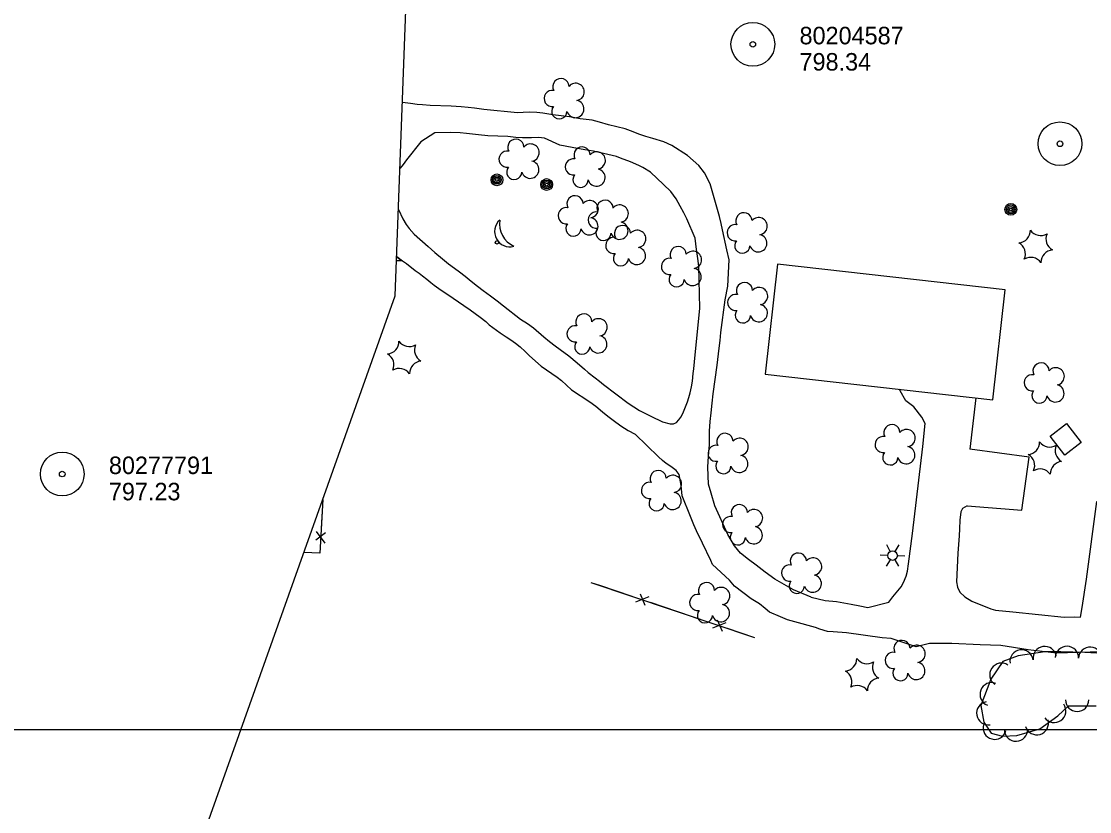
# Model space of a CAD drawing. Extents: x 591954 to 597000, y 198576 to 213500.
# Drawn here: x 593553.2 to 593919.4, y 211471.8 to 211742.7 of the extents above; entities that cross this region are included whole.
import ezdxf

# ---------------------------------------------------------------- set-up
doc = ezdxf.new("R2010")
doc.units = 0
for name, color, linetype in [('Level 10', 7, 'Continuous'), ('Level 12', 7, 'Continuous'), ('Level 14', 7, 'Continuous'), ('Level 15', 7, 'Continuous'), ('Level 17', 7, 'Continuous'), ('Level 18', 7, 'Continuous'), ('Level 4', 7, 'Continuous'), ('Level 6', 7, 'Continuous')]:
    doc.layers.add(name, color=color, linetype=linetype)

msp = doc.modelspace()

# ---------------------------------------------------------------- linework, layer by layer
at = {"layer": 'Level 10'}
msp.add_line((593000, 211500), (595000, 211500), dxfattribs=at)
msp.add_line((593000, 211500), (595000, 211500), dxfattribs=at)
at = {"layer": 'Level 12'}
for points in [[(593890.46, 211650.69), (593812.36, 211659.45), (593808.13, 211621.76), (593886.23, 211612.99), (593890.46, 211650.69)], [(593911.42, 211604.9), (593916.47, 211598.39), (593910.88, 211594.05), (593905.82, 211600.56), (593911.42, 211604.9)]]:
    msp.add_lwpolyline(points, dxfattribs=at)
msp.add_circle((593716.19, 211666.96), 0.562, dxfattribs=at)
for centre, radius, start, end in [((593720.6, 211670.69), 5.22, 131.2001, 285.4985), ((593725.63, 211673.4), 8.55, 171.8557, 244.8398)]:
    msp.add_arc(centre, radius, start, end, dxfattribs=at)
at = {"layer": 'Level 14'}
for p, q in [((593851.02, 211561.02), (593849.83, 211563.32)), ((593852.72, 211561.01), (593854.09, 211563.24)), ((593850.19, 211559.66), (593847.58, 211559.73)), ((593850.94, 211558.17), (593849.58, 211555.98)), ((593852.58, 211558.12), (593853.82, 211555.95)), ((593853.46, 211559.57), (593855.98, 211559.5))]:
    msp.add_line(p, q, dxfattribs=at)
for centre, radius in [((593716.19, 211688.4), 2.02), ((593716.18, 211688.41), 1.52), ((593716.19, 211688.37), 1.01), ((593716.19, 211688.38), 0.502), ((593733.24, 211686.81), 2.02), ((593733.24, 211686.82), 1.52), ((593733.24, 211686.79), 1.01), ((593733.25, 211686.8), 0.502), ((593892.34, 211678.27), 2.02), ((593892.34, 211678.28), 1.52), ((593892.34, 211678.24), 1.01), ((593892.35, 211678.25), 0.502), ((593851.82, 211559.59), 1.64)]:
    msp.add_circle(centre, radius, dxfattribs=at)
at = {"layer": 'Level 15'}
for p, q in [((593657.41, 211567.44), (593654.09, 211564.82)), ((593654.18, 211567.79), (593657.22, 211563.9)), ((593767.06, 211542.46), (593765.42, 211546.35)), ((593768.26, 211545.47), (593763.7, 211543.59)), ((593794.66, 211536.57), (593790.1, 211534.69)), ((593793.46, 211533.56), (593791.83, 211537.45))]:
    msp.add_line(p, q, dxfattribs=at)
for points in [[(593656.52, 211578.79), (593655.53, 211560.45), (593650.05, 211560.61)], [(593656.52, 211578.79), (593655.98, 211568.85)], [(593655.63, 211562.28), (593655.53, 211560.45), (593650.05, 211560.61)], [(593804.64, 211531.37), (593748.48, 211550.3)], [(593751.83, 211549.17), (593748.48, 211550.3)], [(593762.56, 211545.55), (593751.83, 211549.17)], [(593778.24, 211540.27), (593768.8, 211543.45)], [(593788.96, 211536.65), (593778.24, 211540.27)], [(593804.64, 211531.37), (593795.2, 211534.55)]]:
    msp.add_lwpolyline(points, dxfattribs=at)
at = {"layer": 'Level 17'}
for points in [[(593823.89, 211545.38), (593817.91, 211547.86), (593811.51, 211551.53), (593808.15, 211553.86), (593805.06, 211556.26), (593802.43, 211558.19), (593799.65, 211560.45), (593797.64, 211562.88), (593795.29, 211566.82), (593790.87, 211576.64), (593789.6, 211581.03), (593788.73, 211584.07), (593788.53, 211589.94), (593788.74, 211593.67), (593789.07, 211597.61), (593789.02, 211602.25), (593789.28, 211605.59), (593789.64, 211608.54), (593790.03, 211611.84), (593790.3, 211615.03), (593791.74, 211624.89), (593792.39, 211630.71), (593792.76, 211633.36), (593792.97, 211636.12), (593794.39, 211647.25), (593795.34, 211651.93), (593795.77, 211661.01), (593794.95, 211664.4), (593793.48, 211671.31), (593793.08, 211673.5), (593792.44, 211675.83), (593789.28, 211687.07), (593787.31, 211690.86), (593785.43, 211693.31), (593781.49, 211696.72), (593776.2, 211700.22), (593773.36, 211701.48), (593769.62, 211702.57), (593767.2, 211703.27), (593764.89, 211704.08), (593762.85, 211704.9), (593760.15, 211705.86), (593754.46, 211707.33), (593751.34, 211708.22), (593748.89, 211708.83), (593744.73, 211709.38), (593741.11, 211709.96), (593735.36, 211710.68), (593731.93, 211711.25), (593729.83, 211711.48), (593727.29, 211711.57), (593725.24, 211711.5), (593723.22, 211711.38), (593711.71, 211712.48), (593708.55, 211713.04), (593706.37, 211713.23), (593703.89, 211713.41), (593700.49, 211713.65), (593693.33, 211713.93), (593690.66, 211714.15), (593688.8, 211714.3), (593686.59, 211714.6), (593683.84, 211714.97)], [(593694.9, 211704.51), (593690.12, 211701.49), (593685.18, 211695.27), (593684.03, 211693.71), (593683.04, 211692.38), (593682.99, 211692.28)], [(593757.19, 211696.44), (593751.21, 211697.83), (593749.34, 211698.22), (593746.3, 211698.69), (593741.94, 211699.48), (593737.77, 211700.26), (593732.55, 211702.65), (593730.43, 211702.89), (593728.03, 211702.76), (593724.92, 211702.78), (593722.7, 211702.96), (593719.92, 211703.23), (593713.1, 211703.54), (593709.88, 211703.85), (593705.75, 211704.35), (593703.64, 211704.53), (593700.14, 211704.63), (593694.9, 211704.51)], [(593687.78, 211669.82), (593692.58, 211665.59), (593694.92, 211663.51), (593697.55, 211661.29), (593699.58, 211659.67), (593701.61, 211658.15), (593703.34, 211656.86), (593705.26, 211655.35), (593707.38, 211653.68), (593709.54, 211651.95), (593711.5, 211650.47), (593713.98, 211648.67), (593716.31, 211646.9), (593718.45, 211645.2), (593724.3, 211640.67), (593726.65, 211639.11), (593728.68, 211637.68), (593732.22, 211634.57), (593734.16, 211633.02), (593736.16, 211631.51), (593737.86, 211630.27), (593740.84, 211628.03), (593743.65, 211625.7), (593746.21, 211623.45), (593747.5, 211622.39), (593749.86, 211620.54), (593751.41, 211619.36), (593752.76, 211618.28), (593761.17, 211611.85), (593765.12, 211609.38), (593768.93, 211607.44), (593772.94, 211605.5), (593775.53, 211604.75), (593776.76, 211604.71), (593777.77, 211605.24), (593778.56, 211606.08), (593779.26, 211607.05), (593779.9, 211608.28), (593780.88, 211610.6), (593781.51, 211612.29), (593781.96, 211613.79), (593782.46, 211615.4), (593782.9, 211617.41), (593783.2, 211619.4), (593783.49, 211622.02), (593783.68, 211623.63), (593783.89, 211626.03), (593785.72, 211644.45), (593785.39, 211658.82), (593785.05, 211661.46), (593784.61, 211664.52), (593784.17, 211668.37), (593781.3, 211675.08), (593780.3, 211677.11), (593779.06, 211679.4), (593777.62, 211681.86), (593775.86, 211684.45), (593773.32, 211686.85), (593768.89, 211691.01), (593766.25, 211692.64), (593765.07, 211693.19), (593762.81, 211694.24), (593761.36, 211694.81), (593759.18, 211695.66), (593757.19, 211696.44)], [(593682.99, 211692.28), (593682.99, 211692.28)], [(593682.47, 211678.23), (593683.9, 211675.07), (593685.03, 211673.07), (593686.08, 211671.68), (593687.78, 211669.82)], [(593682.47, 211678.23), (593682.47, 211678.23)], [(593681.86, 211662.09), (593683.82, 211660.7), (593681.81, 211660.67)], [(593681.86, 211662.04), (593682.6, 211661.47), (593683.82, 211660.7), (593685.22, 211659.69), (593688.21, 211657.34), (593689.48, 211656.37), (593690.64, 211655.49), (593692.12, 211654.32), (593693.49, 211653.2), (593694.7, 211652.31), (593696.23, 211651.2), (593697.79, 211650.13), (593699.42, 211649.09), (593701.23, 211647.88), (593703.02, 211646.62), (593704.84, 211645.31), (593707, 211643.79), (593708.7, 211642.62), (593710.5, 211641.34), (593712.34, 211639.81), (593713.54, 211638.75), (593717.28, 211635.91), (593719.4, 211634.54), (593720.99, 211633.51), (593722.53, 211632.46), (593724.19, 211631.16), (593725.91, 211629.55), (593727.38, 211628.11), (593731.35, 211624.57), (593734.97, 211622.07), (593736.89, 211620.8), (593738.34, 211619.64), (593741.78, 211616.36), (593748.09, 211612.3), (593750.1, 211610.81), (593752.34, 211608.92), (593754.21, 211607.41), (593756.05, 211606.02), (593758.69, 211604.07), (593761.22, 211602.44), (593763.59, 211601.26)], [(593823.89, 211545.38), (593828.73, 211544.21), (593832.63, 211543.8), (593837.61, 211542.88), (593840.57, 211542.32), (593843.31, 211541.84), (593850.55, 211543.62), (593851.86, 211545.43), (593854.77, 211548.86), (593855.61, 211550.37), (593856.48, 211552.49), (593856.9, 211554.19), (593857.22, 211556.76), (593858.7, 211567.18), (593862.22, 211596.94), (593862.97, 211604.92), (593861.82, 211607.04), (593859.07, 211610.54), (593856.34, 211612.64), (593854.43, 211616.04), (593854.23, 211616.59)], [(593880.33, 211613.66), (593878.33, 211596.1)], [(593825.37, 211534.91), (593818.36, 211536.91), (593815.81, 211537.61), (593813.39, 211538.64), (593809.63, 211540.18), (593808.12, 211541.44), (593806.23, 211542.99), (593803.39, 211544.78), (593797.68, 211549.07), (593795.89, 211551.13), (593790.12, 211556.55), (593789.54, 211557.9), (593786.69, 211563.81), (593784.55, 211568.04), (593783.71, 211570.14), (593782.52, 211572.96), (593779.71, 211580.11), (593779.32, 211583.57), (593778.68, 211587.43), (593777.65, 211588.73), (593775.77, 211590.18), (593774.19, 211591.15), (593772.98, 211592.14), (593771.53, 211593.49), (593763.59, 211601.26)], [(593877.39, 211576.63), (593896.17, 211575.17), (593898.65, 211593.36), (593878.33, 211596.1)], [(593877.39, 211576.63), (593875.75, 211575.69), (593875.16, 211574.57), (593874.82, 211571.75), (593874.74, 211568.76), (593874.69, 211566.31), (593874.15, 211560.46), (593873.78, 211550.59), (593874.05, 211548.77), (593874.92, 211547.08), (593876.6, 211545.47), (593878.98, 211543.99), (593880.38, 211543.4), (593883.51, 211542.11), (593885.54, 211541.34), (593887.14, 211540.9), (593893.06, 211540.27), (593910.61, 211538.44), (593914.14, 211538.54), (593916.25, 211538.52)], [(593916.25, 211538.52), (593916.84, 211541.75), (593918.25, 211551.52), (593921.84, 211578.14), (593941.02, 211576.26), (593952.89, 211575.5), (593970.78, 211573.96)], [(593923.32, 211526.63), (593908.05, 211526.13), (593898.28, 211527.3), (593888.95, 211528.72), (593881.85, 211529.02), (593872.18, 211529.47), (593864.51, 211529.42), (593859.93, 211528.33), (593851.31, 211531.17), (593848.29, 211531.41), (593836, 211533.08), (593831.49, 211533.47), (593829.48, 211533.61), (593826.84, 211534.31), (593825.37, 211534.91)]]:
    msp.add_lwpolyline(points, dxfattribs=at)
at = {"layer": 'Level 18'}
for points in [[(593925.78, 211525.95), (593917.74, 211526.4), (593909.5, 211526.63), (593904.06, 211526.6), (593894.84, 211525.2), (593889.61, 211523.23)], [(593889.61, 211523.23), (593885.55, 211517.17), (593882.05, 211508.2), (593883.05, 211502.43), (593885.61, 211498.74), (593889.51, 211497.72), (593894.36, 211497.85), (593902.26, 211500.24), (593908.5, 211504.67), (593912.09, 211508.02), (593921.59, 211508.06)]]:
    msp.add_lwpolyline(points, dxfattribs=at)
for centre, radius, start, end in [((593738.13, 211720.4), 2.78, 1.3946, 209.1675), ((593735.13, 211716.33), 2.78, 78.0716, 279.0826), ((593743.17, 211718.55), 2.97, 278.4237, 139.6575), ((593743.06, 211712.69), 2.97, 196.0745, 79.0477), ((593737.59, 211711.93), 2.61, 140.7797, 358.7123), ((593722.67, 211699.6), 2.78, 1.3946, 209.1675), ((593727.72, 211697.74), 2.97, 278.4237, 139.6575), ((593719.67, 211695.52), 2.78, 78.0716, 279.0826), ((593745.38, 211696.92), 2.78, 1.3946, 209.1675), ((593750.42, 211695.07), 2.97, 278.4237, 139.6575), ((593722.14, 211691.12), 2.61, 140.7797, 358.7123), ((593727.61, 211691.89), 2.97, 196.0745, 79.0477), ((593742.38, 211692.85), 2.78, 78.0716, 279.0826), ((593744.84, 211688.45), 2.61, 140.7797, 358.7123), ((593750.31, 211689.21), 2.97, 196.0745, 79.0477), ((593742.96, 211680.2), 2.78, 1.3946, 209.1675), ((593739.96, 211676.12), 2.78, 78.0716, 279.0826), ((593748, 211678.34), 2.97, 278.4237, 139.6575), ((593753.25, 211678.69), 2.78, 1.3946, 209.1675), ((593758.29, 211676.84), 2.97, 278.4237, 139.6575), ((593747.89, 211672.49), 2.97, 196.0745, 79.0477), ((593750.25, 211674.62), 2.78, 78.0716, 279.0826), ((593800.86, 211674.37), 2.78, 1.3946, 209.1675), ((593805.9, 211672.51), 2.97, 278.4237, 139.6575), ((593742.42, 211671.72), 2.61, 140.7797, 358.7123), ((593752.71, 211670.22), 2.61, 140.7797, 358.7123), ((593758.18, 211670.98), 2.97, 196.0745, 79.0477), ((593759.25, 211670.02), 2.78, 1.3946, 209.1675), ((593764.29, 211668.16), 2.97, 278.4237, 139.6575), ((593797.86, 211670.29), 2.78, 78.0716, 279.0826), ((593894.75, 211671.07), 4.3, 275.2113, 0.9762), ((593902.57, 211673.63), 4.3, 215.2113, 300.9762), ((593756.25, 211665.94), 2.78, 78.0716, 279.0826), ((593800.32, 211665.89), 2.61, 140.7797, 358.7123), ((593805.79, 211666.66), 2.97, 196.0745, 79.0477), ((593908.69, 211668.13), 4.3, 155.2113, 240.9762), ((593764.18, 211662.31), 2.97, 196.0745, 79.0477), ((593778.34, 211662.82), 2.78, 1.3946, 209.1675), ((593783.38, 211660.97), 2.97, 278.4237, 139.6575), ((593893.06, 211663.03), 4.3, 335.2113, 60.9762), ((593906.99, 211660.09), 4.3, 95.2113, 180.9762), ((593758.71, 211661.54), 2.61, 140.7797, 358.7123), ((593775.34, 211658.75), 2.78, 78.0716, 279.0826), ((593899.17, 211657.54), 4.3, 35.2113, 120.9762), ((593777.8, 211654.35), 2.61, 140.7797, 358.7123), ((593783.27, 211655.11), 2.97, 196.0745, 79.0477), ((593801.04, 211650.43), 2.78, 1.3946, 209.1675), ((593798.04, 211646.35), 2.78, 78.0716, 279.0826), ((593806.08, 211648.57), 2.97, 278.4237, 139.6575), ((593805.97, 211642.71), 2.97, 196.0745, 79.0477), ((593745.98, 211639.71), 2.78, 1.3946, 209.1675), ((593800.5, 211641.95), 2.61, 140.7797, 358.7123), ((593742.98, 211635.63), 2.78, 78.0716, 279.0826), ((593751.03, 211637.85), 2.97, 278.4237, 139.6575), ((593750.92, 211632), 2.97, 196.0745, 79.0477), ((593678.3, 211633), 4.3, 275.2113, 0.9762), ((593686.11, 211635.55), 4.3, 215.2113, 300.9762), ((593692.23, 211630.06), 4.3, 155.2113, 240.9762), ((593745.45, 211631.23), 2.61, 140.7797, 358.7123), ((593676.6, 211624.95), 4.3, 335.2113, 60.9762), ((593682.72, 211619.46), 4.3, 35.2113, 120.9762), ((593690.54, 211622.01), 4.3, 95.2113, 180.9762), ((593902.71, 211622.91), 2.78, 1.3946, 209.1675), ((593907.75, 211621.05), 2.97, 278.4237, 139.6575), ((593899.71, 211618.83), 2.78, 78.0716, 279.0826), ((593902.17, 211614.43), 2.61, 140.7797, 358.7123), ((593907.64, 211615.2), 2.97, 196.0745, 79.0477), ((593794.34, 211598.74), 2.78, 1.3946, 209.1675), ((593851.58, 211601.74), 2.78, 1.3946, 209.1675), ((593856.62, 211599.88), 2.97, 278.4237, 139.6575), ((593791.34, 211594.66), 2.78, 78.0716, 279.0826), ((593799.39, 211596.88), 2.97, 278.4237, 139.6575), ((593848.58, 211597.66), 2.78, 78.0716, 279.0826), ((593897.92, 211598.54), 4.3, 275.2113, 0.9762), ((593905.74, 211601.09), 4.3, 215.2113, 300.9762), ((593911.86, 211595.6), 4.3, 155.2113, 240.9762), ((593799.28, 211591.03), 2.97, 196.0745, 79.0477), ((593851.04, 211593.26), 2.61, 140.7797, 358.7123), ((593856.51, 211594.02), 2.97, 196.0745, 79.0477), ((593896.23, 211590.49), 4.3, 335.2113, 60.9762), ((593793.81, 211590.27), 2.61, 140.7797, 358.7123), ((593910.16, 211587.56), 4.3, 95.2113, 180.9762), ((593771.48, 211586.02), 2.78, 1.3946, 209.1675), ((593776.53, 211584.16), 2.97, 278.4237, 139.6575), ((593902.35, 211585), 4.3, 35.2113, 120.9762), ((593768.48, 211581.94), 2.78, 78.0716, 279.0826), ((593770.95, 211577.54), 2.61, 140.7797, 358.7123), ((593776.42, 211578.31), 2.97, 196.0745, 79.0477), ((593799.3, 211574.3), 2.78, 1.3946, 209.1675), ((593804.34, 211572.45), 2.97, 278.4237, 139.6575), ((593796.3, 211570.23), 2.78, 78.0716, 279.0826), ((593804.23, 211566.59), 2.97, 196.0745, 79.0477), ((593798.76, 211565.83), 2.61, 140.7797, 358.7123), ((593819.53, 211557.69), 2.78, 1.3946, 209.1675), ((593824.57, 211555.83), 2.97, 278.4237, 139.6575), ((593816.53, 211553.61), 2.78, 78.0716, 279.0826), ((593788.04, 211547.57), 2.78, 1.3946, 209.1675), ((593818.99, 211549.21), 2.61, 140.7797, 358.7123), ((593824.46, 211549.98), 2.97, 196.0745, 79.0477), ((593785.04, 211543.5), 2.78, 78.0716, 279.0826), ((593793.08, 211545.72), 2.97, 278.4237, 139.6575), ((593792.97, 211539.86), 2.97, 196.0745, 79.0477), ((593787.5, 211539.1), 2.61, 140.7797, 358.7123), ((593855.03, 211527.75), 2.78, 1.3946, 209.1675), ((593860.07, 211525.89), 2.97, 278.4237, 139.6575), ((593835.26, 211524.27), 4.3, 275.2113, 0.9762), ((593843.08, 211526.83), 4.3, 215.2113, 300.9762), ((593852.03, 211523.68), 2.78, 78.0716, 279.0826), ((593849.2, 211521.34), 4.3, 155.2113, 240.9762), ((593854.49, 211519.28), 2.61, 140.7797, 358.7123), ((593859.96, 211520.04), 2.97, 196.0745, 79.0477), ((593833.57, 211516.23), 4.3, 335.2113, 60.9762), ((593847.5, 211513.29), 4.3, 95.2113, 180.9762), ((593839.69, 211510.74), 4.3, 35.2113, 120.9762)]:
    msp.add_arc(centre, radius, start, end, dxfattribs=at)
for centre, major_axis, ratio, start_param, end_param in [((593903.97, 211524.47), (4, 0.16), 0.998817, 0.110678, 3.252004), ((593911.59, 211524.48), (3.2, -2.4), 0.998935, 0.61648, 3.757805), ((593919.52, 211524.21), (3.9, -0.91), 0.999344, 0.172472, 3.313797), ((593896.06, 211523.27), (4, 0.16), 0.998817, 0.110678, 3.252004), ((593889.12, 211518.74), (2.84, 2.81), 0.997129, 0.200546, 3.341871), ((593885.78, 211512.02), (-0.4, 3.98), 0.996628, 5.810142, 8.951468), ((593884.63, 211505.53), (-2.89, 2.77), 0.997619, 5.648939, 8.790265), ((593915.09, 211510.13), (-3.67, -1.58), 0.999079, 5.880216, 9.021542), ((593907.22, 211506.33), (-3.77, -1.33), 0.997457, 0.278574, 3.419899), ((593901.25, 211502.12), (-3.99, 0.24), 0.998224, 0.353429, 3.494754), ((593886.83, 211500.58), (-3.73, 1.44), 0.999755, 0.11264, 3.253965), ((593894.13, 211499.94), (-3.69, 1.54), 0.998985, 0.424018, 3.565343)]:
    msp.add_ellipse(centre, major_axis=major_axis, ratio=ratio, start_param=start_param, end_param=end_param, dxfattribs=at)
at = {"layer": 'Level 4'}
for points in [[(593681.36, 211648.66), (593703.52, 212242.64)], [(593564.94, 211321.3), (593571.97, 211341.08), (593681.36, 211648.66)]]:
    msp.add_lwpolyline(points, dxfattribs=at)
at = {"layer": 'Level 6'}
for centre, radius in [((593803.92, 211734.88), 7.5), ((593803.92, 211734.88), 0.96), ((593909.2, 211700.78), 7.5), ((593909.2, 211700.78), 0.96), ((593567.18, 211587.54), 7.5), ((593567.18, 211587.54), 0.96)]:
    msp.add_circle(centre, radius, dxfattribs=at)

# ---------------------------------------------------------------- texts
for s, p in [('80204587', (593819.92, 211734.88)), ('798.34', (593819.92, 211725.88)), ('80277791', (593583.18, 211587.54)), ('797.23', (593583.18, 211578.54))]:
    msp.add_text(s, height=6, dxfattribs=at).set_placement(p)

doc.saveas('drawing.dxf')
